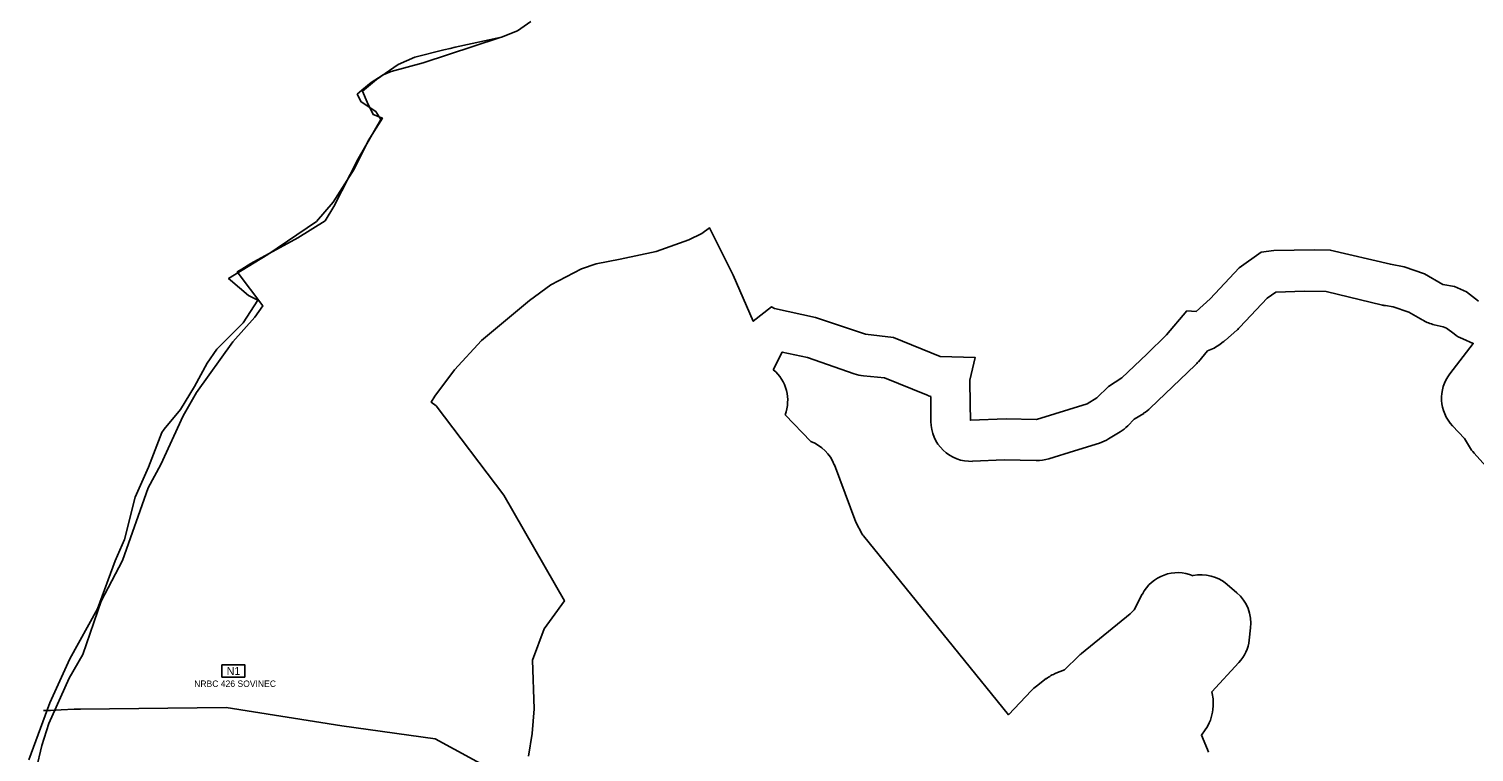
# Model space of a CAD drawing. Extents: x -547623 to -532764, y -1096714 to -1086523.
# Drawn here: x -547591 to -545785, y -1095297 to -1094393 of the extents above; entities that cross this region are included whole.
import ezdxf

# ---------------------------------------------------------------- set-up
doc = ezdxf.new("R2010")
doc.units = 0
for name, color, linetype in [('Vrstva 22', 7, 'Continuous'), ('Vrstva 23', 7, 'Continuous'), ('Vrstva 25', 7, 'Continuous'), ('Vrstva 27', 7, 'Continuous'), ('Vrstva 36', 7, 'Continuous')]:
    doc.layers.add(name, color=color, linetype=linetype)

msp = doc.modelspace()

# ---------------------------------------------------------------- linework, layer by layer
at = {"layer": 'Vrstva 22'}
for points in [[(-546964.3, -1094383.9), (-546980.6, -1094395.6), (-547000.7, -1094403.5), (-547002.5, -1094403.9), (-547003.6, -1094404.6), (-547098.7, -1094435.6), (-547138.9, -1094446.4), (-547148.9, -1094450.6), (-547154.5, -1094454.3), (-547163.5, -1094460.1), (-547175.2, -1094469.9), (-547181.1, -1094475), (-547176, -1094484.5), (-547157.8, -1094496.6), (-547151.5, -1094506.5), (-547179.8, -1094555.6), (-547210.4, -1094615), (-547221.2, -1094633.1), (-547255.3, -1094654.4), (-547314.1, -1094686.4), (-547325.2, -1094693.3), (-547331, -1094696.9), (-547299.1, -1094739.2), (-547309.2, -1094753.3), (-547336.6, -1094784), (-547382.1, -1094847.6), (-547398.8, -1094876.5), (-547426.7, -1094937.4), (-547442.5, -1094966.5), (-547474.6, -1095057.5), (-547501, -1095108.3), (-547524.1, -1095174.8), (-547541.2, -1095204.1), (-547566.5, -1095261), (-547575.4, -1095288.3), (-547582.5, -1095318.3)], [(-546374.7, -1096045.9), (-546376.9, -1096031.7), (-546380.9, -1096022.4), (-546401.2, -1095979), (-546579.1, -1095802.5), (-546630.7, -1095748.9), (-546742.6, -1095608.3), (-546846, -1095459), (-546916.2, -1095394.5), (-547007.9, -1095321.1), (-547083.5, -1095279.9), (-547200.4, -1095263.8), (-547344.8, -1095240.9), (-547527.1, -1095243.1), (-547535, -1095243.2), (-547551.1, -1095243.9), (-547564.5, -1095244.5), (-547572, -1095244.8), (-547573.4, -1095244.8)]]:
    msp.add_lwpolyline(points, dxfattribs=at)
at = {"layer": 'Vrstva 23'}
for p, q in [((-546096.1, -1094782.1), (-546081.6, -1094769.4)), ((-546102.6, -1094787.2), (-546098.8, -1094784.3)), ((-546129.8, -1094809), (-546118.6, -1094795.3)), ((-546189.9, -1094867), (-546133.8, -1094813.2)), ((-546464.2, -1094852.3), (-546464.2, -1094883.5)), ((-546614.2, -1094908.8), (-546646.4, -1094875.3)), ((-546242, -1094905.5), (-546227.7, -1094896.7)), ((-545785.2, -1094923.2), (-545748.3, -1094963.9)), ((-546081.7, -1095097.6), (-546093.9, -1095087.2)), ((-546066.3, -1095156.7), (-546064.5, -1095141.6)), ((-546113.2, -1095221.3), (-546079.3, -1095184.8)), ((-546320, -1095204.9), (-546332.3, -1095214.2)), ((-546111.8, -1095243.3), (-546111.5, -1095238.8))]:
    msp.add_line(p, q, dxfattribs=at)
for points in [[(-546078, -1094765.9), (-546043.9, -1094729.5), (-546033.2, -1094722), (-545997.2, -1094721), (-545970.3, -1094721.1), (-545899.9, -1094738.2)], [(-545896, -1094739), (-545886.4, -1094740.5), (-545866.6, -1094747), (-545849.1, -1094757.3)], [(-545835, -1094762.9), (-545824, -1094765.4), (-545819.7, -1094767.1), (-545810.3, -1094774.3)], [(-545799.4, -1094780.6), (-545786.3, -1094786.1), (-545815.6, -1094824.2)], [(-546661.1, -1094819), (-546649.9, -1094796.9), (-546618.5, -1094803.7), (-546560.1, -1094824.1)], [(-546548.5, -1094826.7), (-546522.3, -1094829.2), (-546469.6, -1094850.5)], [(-546218.1, -1094889.1), (-546210, -1094880.7), (-546198.2, -1094873.5)], [(-545812.3, -1094889.1), (-545797.3, -1094904.9), (-545791.1, -1094915.2)], [(-546316.8, -1094930.2), (-546284.8, -1094920.3), (-546253.5, -1094910.7)], [(-546412, -1094933.4), (-546372.6, -1094931.7), (-546332.5, -1094932.4)], [(-546549.2, -1095025.6), (-546550, -1095024.6), (-546557.9, -1095009.4), (-546584.8, -1094938)], [(-546338.4, -1095219.7), (-546367, -1095249.9), (-546429.1, -1095173.6), (-546548.4, -1095026.6)], [(-546199.9, -1095099.4), (-546210.1, -1095119), (-546215, -1095124), (-546275.8, -1095173.5)], [(-546279.1, -1095176.4), (-546297.2, -1095194), (-546307.9, -1095198.2)], [(-546117.2, -1095296.6), (-546118.5, -1095293.5), (-546126, -1095275.3), (-546121.3, -1095268.9)]]:
    msp.add_lwpolyline(points, dxfattribs=at)
for centre, start, end in [((-545888.1, -1094689.6), 256.3149, 260.9097), ((-546114.5, -1094731.8), 311.236, 316.9116), ((-545823.8, -1094714.1), 239.6568, 257.1219), ((-545780.1, -1094734.5), 232.7981, 247.2703), ((-546132.9, -1094747.4), 286.6202, 307.3039), ((-546129.1, -1094744.5), 307.3039, 311.236), ((-546168.4, -1094777.1), 313.8013, 320.4579), ((-546693.1, -1094857.4), 339.0399, 50.1659), ((-546543.6, -1094776.9), 250.7308, 264.4428), ((-545775.9, -1094854.7), 142.4671, 223.394), ((-546450.9, -1094804.1), 248.0491, 254.5596), ((-546224.5, -1094830.9), 301.6755, 313.8013), ((-546414.2, -1094883.5), 180.0584, 272.5429), ((-546253.8, -1094854.1), 301.5941, 315.57), ((-546631.6, -1094955.6), 20.6882, 69.6103), ((-546268.2, -1094862.9), 287.0706, 301.5941), ((-545748.2, -1094889.6), 210.8353, 222.2028), ((-546331.6, -1094882.4), 268.9544, 287.1706), ((-546587.2, -1095058.1), 39.0498, 40.5752), ((-546155.5, -1095122.5), 67.5694, 152.4689), ((-546126.4, -1095125.2), 49.5378, 101.6093), ((-546114.2, -1095135.7), 353.211, 49.5378), ((-546115.9, -1095150.8), 317.1146, 353.211), ((-546244.2, -1095212.2), 129.1271, 134.1751), ((-546289.8, -1095244.8), 111.2026, 127.1233), ((-546302.1, -1095254.1), 127.1233, 136.6089), ((-546161.3, -1095234.9), 355.4261, 15.7417), ((-546161.7, -1095239.4), 323.8204, 355.4261)]:
    msp.add_arc(centre, 50, start, end, dxfattribs=at)
at = {"layer": 'Vrstva 25'}
for points in [[(-546964.3, -1094383.9), (-546980.6, -1094395.6), (-547000.7, -1094403.5), (-547058.7, -1094416.3), (-547064.9, -1094417.6), (-547073, -1094419.6), (-547109.1, -1094428.7), (-547119.7, -1094433.3), (-547130.1, -1094437.8), (-547156.9, -1094456.7), (-547174.7, -1094471.2), (-547168.7, -1094484.7), (-547161.3, -1094500.2), (-547149.7, -1094504.6), (-547167.6, -1094533.1), (-547185, -1094568.5), (-547211, -1094609.9), (-547231.9, -1094633.8), (-547293, -1094675.2), (-547342, -1094705), (-547339.4, -1094707.2), (-547316.9, -1094726.4), (-547305.2, -1094732.3), (-547323.6, -1094760.5), (-547356.4, -1094793.3), (-547368.6, -1094810.8), (-547384.3, -1094839.8), (-547402.2, -1094868.6), (-547422.3, -1094893.2), (-547425.4, -1094897.3), (-547442.1, -1094940.7), (-547458.5, -1094978), (-547472.1, -1095031.1), (-547483.7, -1095057.9), (-547505.6, -1095117.6), (-547540.1, -1095180.3), (-547565.4, -1095235.1), (-547591.5, -1095306.5)], [(-546966.9, -1095301.9), (-546962.4, -1095273.3), (-546960.1, -1095242.8), (-546962.1, -1095182), (-546947.3, -1095142.5), (-546937.4, -1095128.8), (-546922.1, -1095107.5), (-546997.7, -1094975.5), (-547082.4, -1094864.3), (-547088.5, -1094859.6), (-547084.3, -1094852), (-547059.6, -1094819.1), (-547025.8, -1094782.6), (-546965.9, -1094732.4), (-546939.2, -1094712.9), (-546900.7, -1094693.2), (-546882.4, -1094686.7), (-546852.3, -1094680.8), (-546807.3, -1094671.4), (-546766.5, -1094656.6), (-546750.5, -1094648.9), (-546740.7, -1094641.8), (-546711.1, -1094701), (-546686.1, -1094758.4), (-546663.4, -1094740.6), (-546659.6, -1094742.7), (-546608.2, -1094753.6), (-546545.8, -1094774.7), (-546510.9, -1094778.7), (-546452.4, -1094802.3), (-546408.6, -1094803.9), (-546415.3, -1094831.9), (-546415, -1094862.3), (-546414.7, -1094882.1), (-546370, -1094880.2), (-546332, -1094881.2), (-546268.8, -1094861.7), (-546256.9, -1094854.3), (-546242.1, -1094839.8), (-546225.3, -1094829.3), (-546194.3, -1094799.4), (-546169.5, -1094775.5), (-546144.1, -1094745.5), (-546132.4, -1094746.2), (-546115, -1094730.6), (-546079, -1094691.6), (-546051.5, -1094672), (-546035.4, -1094670.2), (-545984.8, -1094669.3), (-545965, -1094669.6), (-545889.9, -1094687.2), (-545872.5, -1094690.6), (-545847.3, -1094699.1), (-545824.3, -1094712.4), (-545809.7, -1094715.1), (-545794.8, -1094721.6), (-545779.8, -1094733.3)]]:
    msp.add_lwpolyline(points, dxfattribs=at)
at = {"layer": 'Vrstva 27'}
for points in [[(-546964.3, -1094383.9), (-546980.6, -1094395.6), (-547000.7, -1094403.5), (-547058.7, -1094416.3), (-547064.9, -1094417.6), (-547073, -1094419.6), (-547109.1, -1094428.7), (-547119.7, -1094433.3), (-547130.1, -1094437.8), (-547156.9, -1094456.7), (-547174.7, -1094471.2), (-547168.7, -1094484.7), (-547161.3, -1094500.2), (-547149.7, -1094504.6), (-547167.6, -1094533.1), (-547185, -1094568.5), (-547211, -1094609.9), (-547231.9, -1094633.8), (-547293, -1094675.2), (-547342, -1094705), (-547339.4, -1094707.2), (-547316.9, -1094726.4), (-547305.2, -1094732.3), (-547323.6, -1094760.5), (-547356.4, -1094793.3), (-547368.6, -1094810.8), (-547384.3, -1094839.8), (-547402.2, -1094868.6), (-547422.3, -1094893.2), (-547425.4, -1094897.3), (-547442.1, -1094940.7), (-547458.5, -1094978), (-547472.1, -1095031.1), (-547483.7, -1095057.9), (-547505.6, -1095117.6), (-547540.1, -1095180.3), (-547565.4, -1095235.1), (-547591.5, -1095306.5)], [(-546966.9, -1095301.9), (-546962.4, -1095273.3), (-546960.1, -1095242.8), (-546962.1, -1095182), (-546947.3, -1095142.5), (-546937.4, -1095128.8), (-546922.1, -1095107.5), (-546997.7, -1094975.5), (-547082.4, -1094864.3), (-547088.5, -1094859.6), (-547084.3, -1094852), (-547059.6, -1094819.1), (-547025.8, -1094782.6), (-546965.9, -1094732.4), (-546939.2, -1094712.9), (-546900.7, -1094693.2), (-546882.4, -1094686.7), (-546852.3, -1094680.8), (-546807.3, -1094671.4), (-546766.5, -1094656.6), (-546750.5, -1094648.9), (-546740.7, -1094641.8), (-546711.1, -1094701), (-546686.1, -1094758.4), (-546663.4, -1094740.6), (-546659.6, -1094742.7), (-546608.2, -1094753.6), (-546545.8, -1094774.7), (-546510.9, -1094778.7), (-546452.4, -1094802.3), (-546408.6, -1094803.9), (-546415.3, -1094831.9), (-546415, -1094862.3), (-546414.7, -1094882.1), (-546370, -1094880.2), (-546332, -1094881.2), (-546268.8, -1094861.7), (-546256.9, -1094854.3), (-546242.1, -1094839.8), (-546225.3, -1094829.3), (-546194.3, -1094799.4), (-546169.5, -1094775.5), (-546144.1, -1094745.5), (-546132.4, -1094746.2), (-546115, -1094730.6), (-546079, -1094691.6), (-546051.5, -1094672), (-546035.4, -1094670.2), (-545984.8, -1094669.3), (-545965, -1094669.6), (-545889.9, -1094687.2), (-545872.5, -1094690.6), (-545847.3, -1094699.1), (-545824.3, -1094712.4), (-545809.7, -1094715.1), (-545794.8, -1094721.6), (-545779.8, -1094733.3)]]:
    msp.add_lwpolyline(points, dxfattribs=at)
at = {"layer": 'Vrstva 36'}
msp.add_lwpolyline([(-547350.2, -1095187.5), (-547321.6, -1095187.5), (-547321.6, -1095203), (-547350.2, -1095203)], close=True, dxfattribs=at)

# ---------------------------------------------------------------- texts
for s, height, p in [('N1', 10, (-547344.3, -1095200.3)), ('NRBC 426 SOVINEC', 8, (-547384.9, -1095215.2))]:
    msp.add_text(s, height=height, dxfattribs=at).set_placement(p)

doc.saveas('drawing.dxf')
